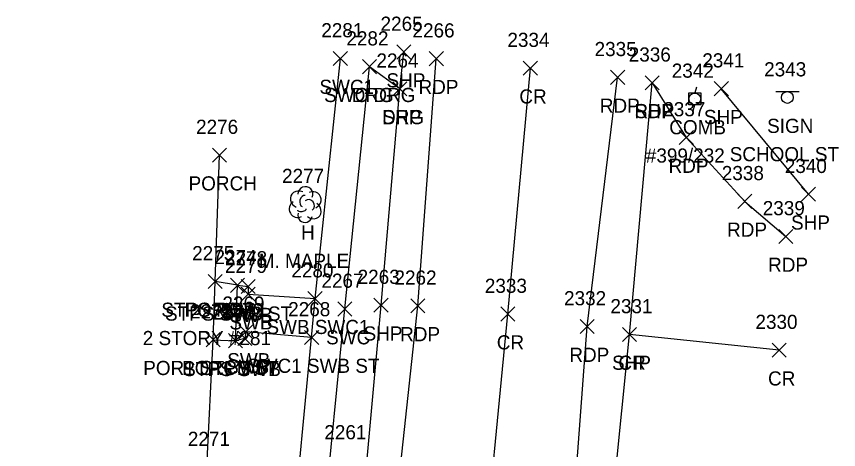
# Model space of a CAD drawing. Extents: x 1653908 to 1654393, y 539913 to 544256.
# Drawn here: x 1654051.4 to 1654167.6, y 542180.1 to 542241.3 of the extents above; entities that cross this region are included whole.
import ezdxf

# ---------------------------------------------------------------- set-up
doc = ezdxf.new("R2010")
doc.units = 0
for name, color, linetype in [('L_A', 7, 'Continuous'), ('L_C', 7, 'Continuous'), ('L_I', 7, 'Continuous'), ('L_TIC', 7, 'Continuous'), ('LBF', 7, 'Continuous'), ('LTD', 7, 'Continuous'), ('P_A', 7, 'Continuous'), ('P_I', 7, 'Continuous'), ('P_TIC', 7, 'Continuous'), ('PET', 7, 'Continuous'), ('PRC', 7, 'Continuous'), ('PSP', 7, 'Continuous'), ('R_A', 7, 'Continuous'), ('R_I', 7, 'Continuous'), ('R_TIC', 7, 'Continuous'), ('RDG', 7, 'Continuous'), ('RSW', 7, 'Continuous'), ('S_A', 7, 'Continuous'), ('S_C', 7, 'Continuous'), ('S_I', 7, 'Continuous'), ('SSGN', 7, 'Continuous'), ('U_A', 7, 'Continuous'), ('U_C', 7, 'Continuous'), ('U_I', 7, 'Continuous'), ('UP', 7, 'Continuous')]:
    doc.layers.add(name, color=color, linetype=linetype)

msp = doc.modelspace()

# ---------------------------------------------------------------- linework, layer by layer
at = {"layer": 'L_TIC'}
for points in [[(1654079.08, 542220.75), (1654081.08, 542222.75)], [(1654081.08, 542220.75), (1654079.08, 542222.75)], [(1654078.48, 542202.89), (1654080.48, 542204.89)], [(1654080.48, 542202.89), (1654078.48, 542204.89)], [(1654078.48, 542202.89), (1654080.48, 542204.89)], [(1654080.48, 542202.89), (1654078.48, 542204.89)], [(1654081.64, 542202.35), (1654083.64, 542204.35)], [(1654083.64, 542202.35), (1654081.64, 542204.35)], [(1654078.18, 542194.66), (1654080.18, 542196.66)], [(1654080.18, 542194.66), (1654078.18, 542196.66)], [(1654078.18, 542194.66), (1654080.18, 542196.66)], [(1654080.18, 542194.66), (1654078.18, 542196.66)], [(1654081.34, 542194.51), (1654083.34, 542196.51)], [(1654083.34, 542194.51), (1654081.34, 542196.51)]]:
    msp.add_lwpolyline(points, dxfattribs=at)
at = {"layer": 'LBF'}
for points in [[(1654078.3, 542177.64), (1654079.18, 542195.66), (1654079.48, 542203.89), (1654080.08, 542221.75)], [(1654079.18, 542195.66), (1654082.34, 542195.51), (1654082.64, 542203.35), (1654079.48, 542203.89)]]:
    msp.add_lwpolyline(points, dxfattribs=at)
at = {"layer": 'LTD'}
msp.add_line((1654092.19, 542214.81), (1654092.19, 542214.81), dxfattribs=at)
msp.add_line((1654092.19, 542214.81), (1654092.19, 542214.81), dxfattribs=at)
msp.add_arc((1654092.23, 542216.24), 1.05, 335.5272, 180.9563, dxfattribs=at)
for centre, major_axis, ratio, start_param, end_param in [((1654091.39, 542215.47), (1.21, -0.51), 0.895232, 1.570796, 4.712389), ((1654091.98, 542215.26), (-0.208, -0.792), 0.645439, 3.141593, 6.283185), ((1654093.23, 542215.39), (-1.14, -0.48), 0.949671, 1.570796, 4.712389), ((1654091.1, 542214.1), (0.58, -1.04), 0.959034, 3.141593, 6.283185), ((1654092.69, 542214.64), (-0.5, 0.667), 0.989748, 3.141593, 6.283185), ((1654091.73, 542214.06), (-0.625, -0.083), 0.423636, 0, 3.141593), ((1654093.19, 542213.97), (-1.09, 0.79), 0.841452, 1.570796, 4.712389), ((1654092.19, 542213.31), (0.26, 1.06), 0.942809, 1.570796, 4.712389)]:
    msp.add_ellipse(centre, major_axis=major_axis, ratio=ratio, start_param=start_param, end_param=end_param, dxfattribs=at)
at = {"layer": 'P_TIC'}
for points in [[(1654105.16, 542235.32), (1654107.16, 542237.32)], [(1654107.16, 542235.32), (1654105.16, 542237.32)], [(1654109.74, 542234.38), (1654111.74, 542236.38)], [(1654111.74, 542234.38), (1654109.74, 542236.38)], [(1654123.05, 542233.04), (1654125.05, 542235.04)], [(1654125.05, 542233.04), (1654123.05, 542235.04)], [(1654135.39, 542231.74), (1654137.39, 542233.74)], [(1654137.39, 542231.74), (1654135.39, 542233.74)], [(1654140.28, 542230.97), (1654142.28, 542232.97)], [(1654142.28, 542230.97), (1654140.28, 542232.97)], [(1654140.28, 542230.97), (1654142.28, 542232.97)], [(1654142.28, 542230.97), (1654140.28, 542232.97)], [(1654104.59, 542230.12), (1654106.59, 542232.12)], [(1654106.59, 542230.12), (1654104.59, 542232.12)], [(1654150.05, 542230.14), (1654152.05, 542232.14)], [(1654152.05, 542230.14), (1654150.05, 542232.14)], [(1654145.1, 542223.24), (1654147.1, 542225.24)], [(1654147.1, 542223.24), (1654145.1, 542225.24)], [(1654153.38, 542214.21), (1654155.38, 542216.21)], [(1654155.38, 542214.21), (1654153.38, 542216.21)], [(1654162.38, 542215.22), (1654164.38, 542217.22)], [(1654164.38, 542215.22), (1654162.38, 542217.22)], [(1654159.18, 542209.25), (1654161.18, 542211.25)], [(1654161.18, 542209.25), (1654159.18, 542211.25)], [(1654101.93, 542199.54), (1654103.93, 542201.54)], [(1654103.93, 542199.54), (1654101.93, 542201.54)], [(1654107.14, 542199.44), (1654109.14, 542201.44)], [(1654109.14, 542199.44), (1654107.14, 542201.44)], [(1654119.87, 542198.28), (1654121.87, 542200.28)], [(1654121.87, 542198.28), (1654119.87, 542200.28)], [(1654131.07, 542196.52), (1654133.07, 542198.52)], [(1654133.07, 542196.52), (1654131.07, 542198.52)], [(1654137.06, 542195.4), (1654139.06, 542197.4)], [(1654139.06, 542195.4), (1654137.06, 542197.4)], [(1654137.06, 542195.4), (1654139.06, 542197.4)], [(1654139.06, 542195.4), (1654137.06, 542197.4)], [(1654158.23, 542193.18), (1654160.23, 542195.18)], [(1654160.23, 542193.18), (1654158.23, 542195.18)]]:
    msp.add_lwpolyline(points, dxfattribs=at)
at = {"layer": 'PET'}
for points in [[(1654079.78, 541659.55), (1654071.38, 541669.62), (1654062.1, 541680.77), (1654062.28, 541682.13), (1654062.95, 541688.2), (1654063.58, 541697.88), (1654065.97, 541728.28), (1654069.39, 541768.38), (1654071.19, 541795.88), (1654073.5, 541821.5), (1654077.02, 541859.14), (1654082.16, 541914.04), (1654084.92, 541947.88), (1654085.88, 541956.64), (1654088.37, 541984.8), (1654091.95, 542029.61), (1654095.3, 542063.75), (1654100.14, 542114.45), (1654103.13, 542154.15), (1654108.14, 542200.44), (1654110.74, 542235.38)], [(1654079.78, 541659.55), (1654080.09, 541663.58), (1654084.43, 541705.04), (1654088.47, 541726.59), (1654090.82, 541750.42), (1654095.24, 541793.92), (1654098.73, 541834.91), (1654102.67, 541873.55), (1654106.19, 541915.36), (1654108.8, 541937.78), (1654112.78, 541976.54), (1654113.71, 541994.76), (1654118.51, 542040.26), (1654122.37, 542081.46), (1654125.51, 542120.57), (1654128.86, 542154.49), (1654132.07, 542197.52), (1654136.39, 542232.74)], [(1654141.28, 542231.97), (1654146.1, 542224.24), (1654154.38, 542215.21), (1654160.18, 542210.25)]]:
    msp.add_lwpolyline(points, dxfattribs=at)
at = {"layer": 'PRC'}
for points in [[(1654071.38, 541669.62), (1654074.69, 541707.08), (1654077.08, 541730.59), (1654080, 541762.22), (1654083.13, 541795.12), (1654087.25, 541836.36), (1654090.63, 541873.54), (1654094.48, 541915.81), (1654096.59, 541938.82), (1654100.21, 541977.67), (1654102.08, 541996.31), (1654106.33, 542040.19), (1654109.98, 542082.61), (1654113.75, 542122.62), (1654117.05, 542159.88), (1654120.87, 542199.28), (1654124.05, 542234.04)], [(1654159.23, 542194.18), (1654138.06, 542196.4)]]:
    msp.add_lwpolyline(points, dxfattribs=at)
at = {"layer": 'PSP'}
for points in [[(1654078.77, 541955.95), (1654079.33, 541984.91), (1654082.06, 542009.12), (1654084.44, 542030.24), (1654088.47, 542064.73), (1654094.99, 542114.99), (1654098.59, 542154.95), (1654100.36, 542172.13), (1654102.93, 542200.54), (1654105.59, 542231.12), (1654106.16, 542236.32)], [(1654094.46, 541721.21), (1654096.1, 541749.59), (1654101.26, 541800.15), (1654104.96, 541834.32), (1654108.51, 541872.88), (1654110.15, 541890.73), (1654111.77, 541915.01), (1654113.74, 541937.09), (1654116.46, 541969.54), (1654117.65, 541994.22), (1654121.74, 542040.28), (1654126.76, 542081.18), (1654129.73, 542120.03), (1654133.66, 542152.74), (1654138.06, 542196.4), (1654141.28, 542231.97)], [(1654163.38, 542216.22), (1654151.05, 542231.14)]]:
    msp.add_lwpolyline(points, dxfattribs=at)
at = {"layer": 'R_TIC'}
for points in [[(1654096.18, 542234.4), (1654098.18, 542236.4)], [(1654098.18, 542234.4), (1654096.18, 542236.4)], [(1654100.29, 542233.25), (1654102.29, 542235.25)], [(1654102.29, 542233.25), (1654100.29, 542235.25)], [(1654100.29, 542233.25), (1654102.29, 542235.25)], [(1654102.29, 542233.25), (1654100.29, 542235.25)], [(1654104.59, 542230.12), (1654106.59, 542232.12)], [(1654106.59, 542230.12), (1654104.59, 542232.12)], [(1654081.64, 542202.35), (1654083.64, 542204.35)], [(1654083.64, 542202.35), (1654081.64, 542204.35)], [(1654083.13, 542202.17), (1654085.13, 542204.17)], [(1654085.13, 542202.17), (1654083.13, 542204.17)], [(1654083.13, 542201.1), (1654085.13, 542203.1)], [(1654085.13, 542201.1), (1654083.13, 542203.1)], [(1654092.6, 542200.46), (1654094.6, 542202.46)], [(1654094.6, 542200.46), (1654092.6, 542202.46)], [(1654092.6, 542200.46), (1654094.6, 542202.46)], [(1654094.6, 542200.46), (1654092.6, 542202.46)], [(1654096.8, 542199), (1654098.8, 542201)], [(1654098.8, 542199), (1654096.8, 542201)], [(1654082.81, 542195.76), (1654084.81, 542197.76)], [(1654084.81, 542195.76), (1654082.81, 542197.76)], [(1654081.34, 542194.51), (1654083.34, 542196.51)], [(1654083.34, 542194.51), (1654081.34, 542196.51)], [(1654082.66, 542194.84), (1654084.66, 542196.84)], [(1654084.66, 542194.84), (1654082.66, 542196.84)], [(1654092.11, 542194.97), (1654094.11, 542196.97)], [(1654094.11, 542194.97), (1654092.11, 542196.97)], [(1654092.11, 542194.97), (1654094.11, 542196.97)], [(1654094.11, 542194.97), (1654092.11, 542196.97)]]:
    msp.add_lwpolyline(points, dxfattribs=at)
at = {"layer": 'RDG'}
msp.add_lwpolyline([(1654105.59, 542231.12), (1654101.29, 542234.25)], dxfattribs=at)
at = {"layer": 'RSW'}
for points in [[(1654051.37, 541872.29), (1654052.46, 541871.5), (1654066.16, 541870.17), (1654068.18, 541915.93), (1654069.75, 541944.22), (1654070.31, 541953.54), (1654072.79, 541983.02), (1654073.08, 541986.24), (1654077.36, 542031.04), (1654080.59, 542065.12), (1654085.44, 542116.23), (1654086.21, 542120.5), (1654089.27, 542157.54), (1654090.31, 542166.74), (1654093.11, 542195.97), (1654093.6, 542201.46), (1654097.18, 542235.4)], [(1654068.64, 541821.64), (1654069.31, 541838.71), (1654070.52, 541867.73), (1654072.55, 541915.29), (1654073.84, 541942.17), (1654076.05, 541941.96), (1654076.98, 541955.53), (1654075.17, 541955.84), (1654077.56, 541985.56), (1654081.72, 542030.54), (1654085.05, 542064.96), (1654089.27, 542115.61), (1654093.43, 542156.15), (1654094.75, 542169), (1654097.8, 542200), (1654101.29, 542234.25)], [(1654082.64, 542203.35), (1654084.13, 542203.17), (1654084.13, 542202.1), (1654093.6, 542201.46)], [(1654093.11, 542195.97), (1654083.81, 542196.76), (1654083.66, 542195.84), (1654082.34, 542195.51)]]:
    msp.add_lwpolyline(points, dxfattribs=at)
at = {"layer": 'SSGN'}
for p, q in [((1654158.74, 542230.73), (1654162.08, 542230.73)), ((1654160.39, 542229.9), (1654160.39, 542229.9))]:
    msp.add_line(p, q, dxfattribs=at)
msp.add_circle((1654160.39, 542229.9), 0.833, dxfattribs=at)
at = {"layer": 'UP'}
for p, q in [((1654147.55, 542231.36), (1654147.3, 542230.53)), ((1654146.47, 542228.86), (1654146.47, 542230.53)), ((1654146.47, 542230.53), (1654148.14, 542230.53)), ((1654148.14, 542230.53), (1654148.14, 542228.86)), ((1654147.3, 542229.69), (1654147.3, 542229.69)), ((1654148.14, 542228.86), (1654146.47, 542228.86)), ((1654147.05, 542228.03), (1654147.3, 542228.86))]:
    msp.add_line(p, q, dxfattribs=at)
msp.add_circle((1654147.3, 542229.69), 0.833, dxfattribs=at)

# ---------------------------------------------------------------- texts
at = {"layer": 'L_A'}
for s, p in [('PORCH', (1654075.71, 542216.75)), ('H', (1654091.62, 542209.81)), ('STPS POR1', (1654071.86, 542198.89)), ('STPS SWB ST', (1654072.38, 542198.35)), ('PORCH', (1654075.11, 542198.89)), ('POR1 STPS ST', (1654069.3, 542190.66)), ('PORCH', (1654074.8, 542190.66)), ('STPS SWB', (1654074.94, 542190.51))]:
    msp.add_text(s, height=2, dxfattribs=at).set_placement(p)
at = {"layer": 'L_C'}
for s, p in [('M. MAPLE', (1654085.64, 542205.81)), ('2 STORY #281', (1654069.23, 542194.89))]:
    msp.add_text(s, height=2, dxfattribs=at).set_placement(p)
at = {"layer": 'L_I'}
for s, p in [('2276', (1654076.77, 542224.75)), ('2277', (1654088.93, 542217.81)), ('2275', (1654076.22, 542206.89)), ('2275', (1654076.22, 542206.89)), ('2274', (1654079.38, 542206.35)), ('2272', (1654075.92, 542198.66)), ('2272', (1654075.92, 542198.66)), ('2273', (1654079.08, 542198.51)), ('2271', (1654075.61, 542180.64))]:
    msp.add_text(s, height=2, dxfattribs=at).set_placement(p)
at = {"layer": 'P_A'}
for s, p in [('SHP', (1654103.7, 542231.32)), ('RDP', (1654108.23, 542230.38)), ('CR', (1654122.49, 542229.04)), ('RDP', (1654133.87, 542227.74)), ('SHP', (1654138.81, 542226.97)), ('RDP', (1654138.76, 542226.97)), ('SHP', (1654103.12, 542226.12)), ('SHP', (1654148.59, 542226.14)), ('RDP', (1654143.59, 542219.24)), ('SHP', (1654160.91, 542211.22)), ('RDP', (1654151.87, 542210.21)), ('RDP', (1654157.67, 542205.25)), ('SHP', (1654100.46, 542195.54)), ('RDP', (1654105.63, 542195.44)), ('CR', (1654119.3, 542194.28)), ('RDP', (1654129.56, 542192.52)), ('SHP', (1654135.6, 542191.4)), ('CR', (1654136.5, 542191.4)), ('CR', (1654157.66, 542189.18))]:
    msp.add_text(s, height=2, dxfattribs=at).set_placement(p)
at = {"layer": 'P_I'}
for s, p in [('2265', (1654102.86, 542239.32)), ('2266', (1654107.38, 542238.38)), ('2334', (1654120.8, 542237.04)), ('2335', (1654133.13, 542235.74)), ('2264', (1654102.28, 542234.12)), ('2336', (1654137.96, 542234.97)), ('2336', (1654137.96, 542234.97)), ('2341', (1654148.36, 542234.14)), ('2337', (1654142.84, 542227.24)), ('2340', (1654160.03, 542219.22)), ('2338', (1654151.12, 542218.21)), ('2339', (1654156.91, 542213.25)), ('2263', (1654099.62, 542203.54)), ('2262', (1654104.83, 542203.44)), ('2333', (1654117.61, 542202.28)), ('2332', (1654128.81, 542200.52)), ('2331', (1654135.37, 542199.4)), ('2331', (1654135.37, 542199.4)), ('2330', (1654155.88, 542197.18))]:
    msp.add_text(s, height=2, dxfattribs=at).set_placement(p)
at = {"layer": 'R_A'}
for s, p in [('SWC1', (1654094.22, 542230.4)), ('SWC DRG', (1654094.87, 542229.25)), ('DRG', (1654098.78, 542229.25)), ('DRG', (1654103.08, 542226.12)), ('STPS SWB ST', (1654072.38, 542198.35)), ('SWB', (1654081.49, 542198.17)), ('SWB', (1654081.49, 542197.1)), ('SWB SWC1', (1654086.73, 542196.46)), ('SWB SWC1', (1654086.73, 542196.46)), ('SWC', (1654095.16, 542195)), ('SWB', (1654081.02, 542190.84)), ('SWB', (1654081.18, 542191.76)), ('SWC1 SWB ST', (1654083.99, 542190.97)), ('SWC1 SWB ST', (1654083.99, 542190.97)), ('STPS SWB', (1654074.94, 542190.51))]:
    msp.add_text(s, height=2, dxfattribs=at).set_placement(p)
at = {"layer": 'R_I'}
for s, p in [('2281', (1654094.48, 542238.4)), ('2282', (1654098.03, 542237.25)), ('2282', (1654098.03, 542237.25)), ('2264', (1654102.28, 542234.12)), ('2274', (1654079.38, 542206.35)), ('2278', (1654080.87, 542206.17)), ('2279', (1654080.86, 542205.1)), ('2280', (1654090.25, 542204.46)), ('2280', (1654090.25, 542204.46)), ('2267', (1654094.5, 542203)), ('2269', (1654080.5, 542199.76)), ('2268', (1654089.8, 542198.97)), ('2268', (1654089.8, 542198.97)), ('2273', (1654079.08, 542198.51)), ('2270', (1654080.31, 542198.84))]:
    msp.add_text(s, height=2, dxfattribs=at).set_placement(p)
at = {"layer": 'S_A'}
msp.add_text('SIGN', height=2, dxfattribs=at).set_placement((1654157.53, 542224.88))
at = {"layer": 'S_C'}
msp.add_text('SCHOOL ST', height=2, dxfattribs=at).set_placement((1654152.24, 542220.88))
at = {"layer": 'S_I'}
for s, p in [('2343', (1654157.11, 542232.88)), ('2261', (1654094.91, 542181.58))]:
    msp.add_text(s, height=2, dxfattribs=at).set_placement(p)
at = {"layer": 'U_A'}
msp.add_text('COMB', height=2, dxfattribs=at).set_placement((1654143.69, 542224.69))
at = {"layer": 'U_C'}
msp.add_text('#399/232', height=2, dxfattribs=at).set_placement((1654140.38, 542220.69))
at = {"layer": 'U_I'}
msp.add_text('2342', height=2, dxfattribs=at).set_placement((1654144.04, 542232.69))

doc.saveas('drawing.dxf')
